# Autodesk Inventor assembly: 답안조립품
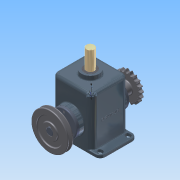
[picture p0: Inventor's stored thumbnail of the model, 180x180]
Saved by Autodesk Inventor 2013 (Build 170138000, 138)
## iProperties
Created: 2015-03
Part Number: 답안조립품
Document SubType Name: Assembly
Designer: Administrator
Mass: 8579.28 g
Surface Area: 4386.42 cm^2
Volume: 1982.54 cm^3
Density: 4.32742 g/cm^3
Author: Administrator
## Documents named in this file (15)
- C:\Documents and Settings\Administrator\바탕 화면\350305V1027\답안조립품.iam
- C:\Documents and Settings\Administrator\바탕 화면\350305V1027\본체.ipt
- C:\Documents and Settings\Administrator\바탕 화면\350305V1027\체인 스프로킷.ipt
- C:\Documents and Settings\Administrator\바탕 화면\350305V1027\커버.ipt
- C:\Documents and Settings\Administrator\바탕 화면\350305V1027\베어링 6205.ipt
- C:\Documents and Settings\Administrator\바탕 화면\350305V1027\오일실.ipt
- C:\Documents and Settings\Administrator\바탕 화면\350305V1027\편심축.ipt
- C:\Documents and Settings\Administrator\바탕 화면\350305V1027\멈춤나사 M5x0.5.ipt
- C:\Documents and Settings\Administrator\바탕 화면\350305V1027\키 8x8.ipt
- C:\Documents and Settings\Administrator\바탕 화면\350305V1027\M4x0.5.ipt
- C:\Documents and Settings\Administrator\바탕 화면\350305V1027\멈춤링.ipt
- C:\Documents and Settings\Administrator\바탕 화면\350305V1027\V-벨트풀리.ipt
- C:\Documents and Settings\Administrator\바탕 화면\350305V1027\부시.ipt
- C:\Documents and Settings\Administrator\바탕 화면\350305V1027\7-가변스프링.ipt
- C:\Documents and Settings\Administrator\바탕 화면\350305V1027\슬라이드.ipt
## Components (9 placed, 4 different names)
1. 5-체인 스프로킷:1 — 플러쉬:2, 각도:2
2. V-벨트풀리:1 — 플러쉬:4, 각도:4
3. 7-가변스프링:1
4. M4x0.5:1
5. M4x0.5:2
6. M4x0.5:3
7. M4x0.5:4
8. M4x0.5:5
9. M4x0.5:6
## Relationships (4: Flush 2, Angle 2)
- 플러쉬:2 [Flush]: 5-체인 스프로킷:1
- 각도:2 [Angle]: 5-체인 스프로킷:1
- 플러쉬:4 [Flush]: V-벨트풀리:1
- 각도:4 [Angle]: V-벨트풀리:1
